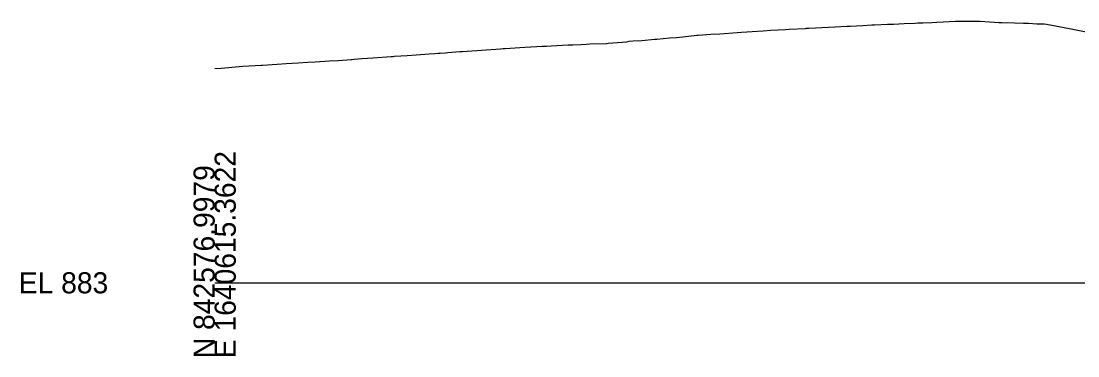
# Model space of a CAD drawing. Extents: x -26 to 1640245, y -10 to 842531.
# Drawn here: x -25.7 to 114.6, y -9.7 to 34.7 of the extents above; entities that cross this region are included whole.
import ezdxf

# ---------------------------------------------------------------- set-up
doc = ezdxf.new("R2010")
doc.units = 0
for name, color, linetype in [('Default', 7, 'Continuous'), ('Exist Cross Section Cell', 7, 'Continuous'), ('Exist XS Ground Line', 7, 'Continuous'), ('Scratch_Level_0', 7, 'Continuous')]:
    doc.layers.add(name, color=color, linetype=linetype)

msp = doc.modelspace()

# ---------------------------------------------------------------- linework, layer by layer
at = {"layer": 'Exist Cross Section Cell'}
msp.add_line((0, 0), (150, 0), dxfattribs=at)
at = {"layer": 'Exist XS Ground Line'}
for p, q in [((76.27, 33.65), (78.45, 33.76)), ((78.45, 33.76), (78.59, 33.77)), ((78.59, 33.77), (78.88, 33.79)), ((78.88, 33.79), (81.47, 33.93)), ((81.47, 33.93), (82.36, 33.97)), ((82.36, 33.97), (83.92, 34.04)), ((83.92, 34.04), (84.19, 34.05)), ((84.19, 34.05), (84.35, 34.06)), ((84.35, 34.06), (86.03, 34.16)), ((86.03, 34.16), (87.23, 34.22)), ((87.23, 34.22), (87.56, 34.24)), ((87.56, 34.24), (87.6, 34.24)), ((87.6, 34.24), (89.32, 34.3)), ((89.32, 34.3), (90.1, 34.33)), ((90.1, 34.33), (91.52, 34.4)), ((91.52, 34.4), (92.98, 34.47)), ((92.98, 34.47), (93.36, 34.48)), ((93.36, 34.48), (94.01, 34.51)), ((94.01, 34.51), (95.19, 34.56)), ((95.19, 34.56), (95.86, 34.59)), ((95.86, 34.59), (98.33, 34.7)), ((98.33, 34.7), (98.74, 34.72)), ((98.74, 34.72), (98.85, 34.72)), ((98.85, 34.72), (99.59, 34.72)), ((99.59, 34.72), (100.13, 34.72)), ((100.13, 34.72), (101.62, 34.71)), ((101.62, 34.71), (104.09, 34.56)), ((104.09, 34.56), (104.5, 34.54)), ((104.5, 34.54), (106.18, 34.48)), ((106.18, 34.48), (107.38, 34.44)), ((107.38, 34.44), (108.02, 34.43)), ((108.02, 34.43), (109.13, 34.38)), ((109.13, 34.38), (110.14, 34.34)), ((110.14, 34.34), (110.42, 34.32)), ((110.42, 34.32), (112.55, 33.92)), ((112.55, 33.92), (116.64, 33.11)), ((56.71, 32.14), (58.44, 32.31)), ((58.44, 32.31), (58.71, 32.33)), ((58.71, 32.33), (60.37, 32.49)), ((60.37, 32.49), (61.32, 32.56)), ((61.32, 32.56), (62.56, 32.69)), ((62.56, 32.69), (62.91, 32.73)), ((62.91, 32.73), (64.01, 32.85)), ((64.01, 32.85), (64.19, 32.86)), ((64.19, 32.86), (65.87, 32.97)), ((65.87, 32.97), (67.07, 33.05)), ((67.07, 33.05), (67.7, 33.1)), ((67.7, 33.1), (68.8, 33.17)), ((68.8, 33.17), (69.95, 33.24)), ((69.95, 33.24), (71.37, 33.34)), ((71.37, 33.34), (72.83, 33.43)), ((72.83, 33.43), (73.84, 33.5)), ((73.84, 33.5), (75.78, 33.63)), ((75.78, 33.63), (76.27, 33.65)), ((33.5, 30.74), (35.41, 30.88)), ((35.41, 30.88), (37.94, 31.06)), ((37.94, 31.06), (38.29, 31.08)), ((38.29, 31.08), (38.55, 31.1)), ((38.55, 31.1), (41.16, 31.27)), ((41.16, 31.27), (42.79, 31.36)), ((42.79, 31.36), (43.49, 31.4)), ((43.49, 31.4), (43.92, 31.39)), ((43.92, 31.39), (44.04, 31.4)), ((44.04, 31.4), (44.65, 31.43)), ((44.65, 31.43), (46.92, 31.56)), ((46.92, 31.56), (47.54, 31.58)), ((47.54, 31.58), (48.63, 31.64)), ((48.63, 31.64), (49.38, 31.67)), ((49.38, 31.67), (49.8, 31.69)), ((49.8, 31.69), (52, 31.77)), ((52, 31.77), (52.07, 31.77)), ((52.07, 31.77), (52.22, 31.78)), ((52.22, 31.78), (54.72, 31.97)), ((54.72, 31.97), (55.03, 32.06)), ((55.03, 32.06), (55.56, 32.1)), ((55.56, 32.1), (56.71, 32.14)), ((15.26, 29.44), (16.39, 29.51)), ((16.39, 29.51), (18.13, 29.64)), ((18.13, 29.64), (18.2, 29.65)), ((18.2, 29.65), (18.51, 29.66)), ((18.51, 29.66), (19.57, 29.74)), ((19.57, 29.74), (21.01, 29.85)), ((21.01, 29.85), (23.42, 30.02)), ((23.42, 30.02), (23.72, 30.04)), ((23.72, 30.04), (23.89, 30.05)), ((23.89, 30.05), (25.55, 30.16)), ((25.55, 30.16), (26.77, 30.24)), ((26.77, 30.24), (28.46, 30.36)), ((28.46, 30.36), (29.22, 30.42)), ((29.22, 30.42), (29.65, 30.45)), ((29.65, 30.45), (29.95, 30.47)), ((29.95, 30.47), (30.63, 30.53)), ((30.63, 30.53), (30.97, 30.55)), ((30.97, 30.55), (32.53, 30.67)), ((32.53, 30.67), (32.88, 30.7)), ((32.88, 30.7), (33.5, 30.74)), ((0, 28.42), (0.86, 28.47)), ((0.86, 28.47), (3.25, 28.69)), ((3.25, 28.69), (3.74, 28.73)), ((3.74, 28.73), (6.21, 28.88)), ((6.21, 28.88), (6.28, 28.88)), ((6.28, 28.88), (6.35, 28.89)), ((6.35, 28.89), (8.29, 29)), ((8.29, 29), (9.5, 29.08)), ((9.5, 29.08), (11.1, 29.18)), ((11.1, 29.18), (12.38, 29.27)), ((12.38, 29.27), (13.34, 29.32)), ((13.34, 29.32), (15.26, 29.44))]:
    msp.add_line(p, q, dxfattribs=at)

# ---------------------------------------------------------------- texts
at = {"layer": 'Default'}
msp.add_text('-', height=0.0001, dxfattribs=at).set_placement((0, 0))
at = {"layer": 'Exist Cross Section Cell'}
for s, p in [('E 1640615.3622', (2.8, -10)), ('N 842576.9979', (0, -10))]:
    msp.add_text(s, height=2.8, rotation=90, dxfattribs=at).set_placement(p)
msp.add_text('EL 883', height=2.8, dxfattribs=at).set_placement((-26, -1.4))
at = {"layer": 'Scratch_Level_0'}
for s, p in [('Exterior Boundary', (106.58, 34.46)), ('LT_Slope_Cut', (106.6, 34.46))]:
    msp.add_text(s, height=0.01, dxfattribs=at).set_placement(p)

doc.saveas('drawing.dxf')
